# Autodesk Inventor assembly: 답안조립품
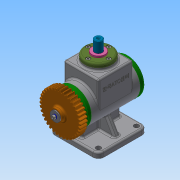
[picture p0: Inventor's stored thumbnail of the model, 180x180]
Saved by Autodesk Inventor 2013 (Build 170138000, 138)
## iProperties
Created: 2019-01
Part Number: 답안조립품
Document SubType Name: Assembly
Designer: Administrator
Mass: 1743.45 g
Surface Area: 1517.22 cm^2
Volume: 492.002 cm^3
Density: 3.54358 g/cm^3
Author: Administrator
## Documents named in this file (18)
- C:\Users\Administrator\Desktop\390107V1026\답안조립품.iam
- C:\Users\Administrator\Desktop\390107V1026\본체.ipt
- C:\Users\Administrator\Desktop\390107V1026\베어링 6203.ipt
- C:\Users\Administrator\Desktop\390107V1026\뒤커버.ipt
- C:\Users\Administrator\Desktop\390107V1026\볼트 M4.ipt
- C:\Users\Administrator\Desktop\390107V1026\편심축.ipt
- C:\Users\Administrator\Desktop\390107V1026\키 4x4x12.ipt
- C:\Users\Administrator\Desktop\390107V1026\앞커버.ipt
- C:\Users\Administrator\Desktop\390107V1026\오일 실 17 30 5.ipt
- C:\Users\Administrator\Desktop\390107V1026\스퍼기어.ipt
- C:\Users\Administrator\Desktop\390107V1026\평와셔.ipt
- C:\Users\Administrator\Desktop\390107V1026\스프링와셔.ipt
- C:\Users\Administrator\Desktop\390107V1026\슬라이더.ipt
- C:\Users\Administrator\Desktop\390107V1026\상부커버.ipt
- C:\Users\Administrator\Desktop\390107V1026\부시.ipt
- C:\Users\Administrator\Desktop\390107V1026\멈춤링.ipt
- C:\Users\Administrator\Desktop\390107V1026\스프링조립용 와셔.ipt
- C:\Users\Administrator\Desktop\390107V1026\가변스프링.ipt
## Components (1 placed, 1 different names)
1. 가변스프링:1
